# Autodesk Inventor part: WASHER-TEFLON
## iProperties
Created: 2007-10
Part Number: WASHER-TEFLON
Document SubType Name: Modeling
Material: Delrin, White
Density: 1.42 g/cm^3
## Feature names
1. Base1
